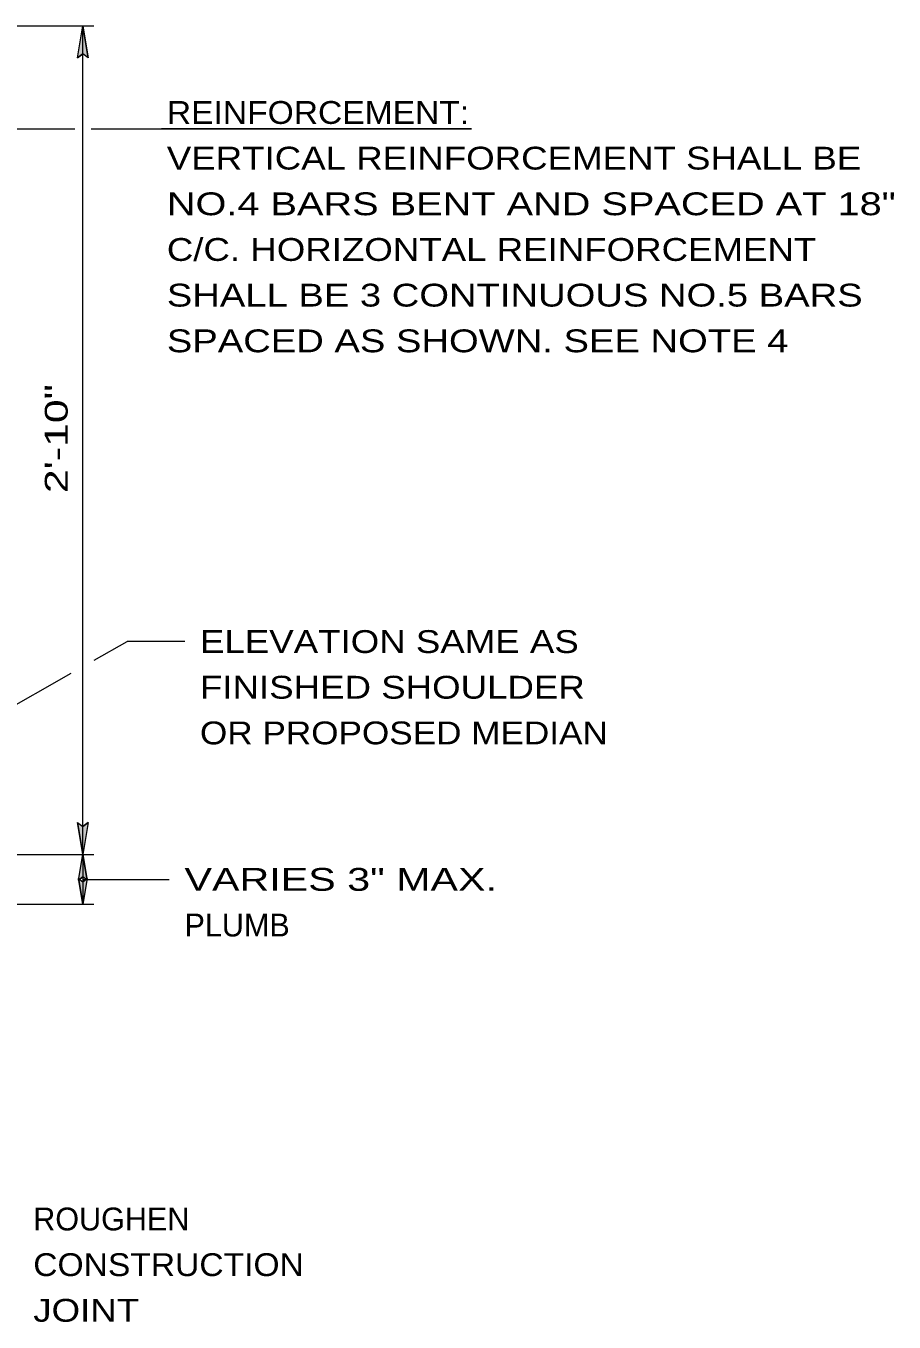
# Model space of a CAD drawing. Extents: x -9.07 to -2.08, y 8.04 to 17.77.
# Drawn here: x -4.365 to -2.084, y 13.191 to 16.597 of the extents above; entities that cross this region are included whole.
import ezdxf
from ezdxf.enums import TextEntityAlignment as Align

# ---------------------------------------------------------------- set-up
doc = ezdxf.new("R2010")
doc.units = 0
doc.header["$LTSCALE"] = 0.024
doc.layers.add('10', color=7, linetype='Continuous', lineweight=13)
doc.layers.add('12', color=7, linetype='Continuous', lineweight=53)

msp = doc.modelspace()

# ---------------------------------------------------------------- hatches: boundary and pattern name
at = {"layer": '10'}
for points in [[(-4.21517, 16.59717), (-4.20117, 16.51317), (-4.21517, 16.52367), (-4.22917, 16.51317)], [(-4.20117, 14.50383), (-4.21517, 14.41983), (-4.22917, 14.50383), (-4.21517, 14.49333)], [(-4.21517, 14.41983), (-4.204, 14.3525), (-4.21517, 14.361), (-4.2265, 14.3525)], [(-4.21517, 14.34833), (-4.204, 14.35667), (-4.21517, 14.2895), (-4.2265, 14.35667)]]:
    msp.add_hatch(color=256, dxfattribs=at).paths.add_polyline_path(points)

# ---------------------------------------------------------------- linework, layer by layer
for p, q in [((-5.17817, 16.59717), (-4.18633, 16.59717)), ((-4.22917, 16.51317), (-4.21517, 16.59717)), ((-4.20117, 16.51317), (-4.21517, 16.59717)), ((-4.22917, 16.51317), (-4.21517, 16.52367)), ((-4.20117, 16.51317), (-4.21517, 16.52367)), ((-4.59267, 16.32633), (-4.23683, 16.32633)), ((-4.19367, 16.32633), (-4.00833, 16.32633)), ((-4.18517, 14.9305), (-4.09883, 14.9795)), ((-3.94767, 14.9795), (-4.09883, 14.9795)), ((-4.58117, 14.706), (-4.24567, 14.89617)), ((-4.22917, 14.50383), (-4.21517, 14.41983)), ((-4.22917, 14.50383), (-4.21517, 14.49333)), ((-4.20117, 14.50383), (-4.21517, 14.41983)), ((-4.20117, 14.50383), (-4.21517, 14.49333)), ((-4.72083, 14.41983), (-4.18633, 14.41983)), ((-4.2265, 14.3525), (-4.21517, 14.41983)), ((-4.21517, 14.41983), (-4.21517, 14.2895)), ((-4.204, 14.3525), (-4.21517, 14.41983)), ((-4.2265, 14.3525), (-4.21517, 14.361)), ((-4.2265, 14.35667), (-4.21517, 14.2895)), ((-4.2265, 14.35667), (-4.21517, 14.34833)), ((-4.204, 14.3525), (-4.21517, 14.361)), ((-4.204, 14.35667), (-4.21517, 14.2895)), ((-4.204, 14.35667), (-4.21517, 14.34833)), ((-4.21517, 14.35467), (-3.98833, 14.35467)), ((-4.3955, 14.2895), (-4.18633, 14.2895))]:
    msp.add_line(p, q, dxfattribs=at)
at = {"layer": '10', "lineweight": 25}
msp.add_line((-4.00833, 16.32633), (-3.19433, 16.32633), dxfattribs=at)
at = {"layer": '10'}
for points in [[(-4.21517, 16.59717), (-4.20117, 16.51317), (-4.21517, 16.52367), (-4.22917, 16.51317)], [(-4.20117, 14.50383), (-4.21517, 14.41983), (-4.22917, 14.50383), (-4.21517, 14.49333)], [(-4.21517, 14.41983), (-4.204, 14.3525), (-4.21517, 14.361), (-4.2265, 14.3525)], [(-4.21517, 14.34833), (-4.204, 14.35667), (-4.21517, 14.2895), (-4.2265, 14.35667)]]:
    msp.add_lwpolyline(points, close=True, dxfattribs=at)
msp.add_lwpolyline([(-4.21517, 14.41983), (-4.21517, 16.32717), (-4.21517, 16.59717)], dxfattribs=at)

# ---------------------------------------------------------------- texts
at = {"layer": '12'}
for s, width, p in [('REINFORCEMENT:', 1.1, (-3.99467, 16.33975)), ('VERTICAL REINFORCEMENT SHALL BE', 1.2, (-3.99467, 16.21975)), ('NO.4 BARS BENT AND SPACED AT 18"', 1.3, (-3.99467, 16.09975)), ('C/C. HORIZONTAL REINFORCEMENT', 1.2, (-3.99467, 15.97975)), ('SHALL BE 3 CONTINUOUS NO.5 BARS', 1.25, (-3.99467, 15.85975)), ('SPACED AS SHOWN. SEE NOTE 4', 1.25, (-3.99467, 15.73967)), ('ELEVATION SAME AS', 1.2, (-3.90758, 14.94942)), ('FINISHED SHOULDER', 1.2, (-3.90758, 14.82942)), ('OR PROPOSED MEDIAN', 1.15, (-3.90758, 14.70942)), ('VARIES 3" MAX.', 1.35, (-3.94825, 14.32458)), ('CONSTRUCTION', 1.1, (-4.34567, 13.31217)), ('JOINT', 1.2, (-4.34567, 13.19217))]:
    msp.add_text(s, height=0.06001, dxfattribs=dict(at, width=width)).set_placement(p)
at = {"layer": '12', "width": 1.4}
msp.add_text('2\'-10"', height=0.06001, rotation=90, dxfattribs=at).set_placement((-4.25525, 15.51267), align=Align.CENTER)
at = {"layer": '12'}
for s, p in [('PLUMB', (-3.94825, 14.20458)), ('ROUGHEN', (-4.34567, 13.43217))]:
    msp.add_text(s, height=0.06001, dxfattribs=at).set_placement(p)

doc.saveas('drawing.dxf')
